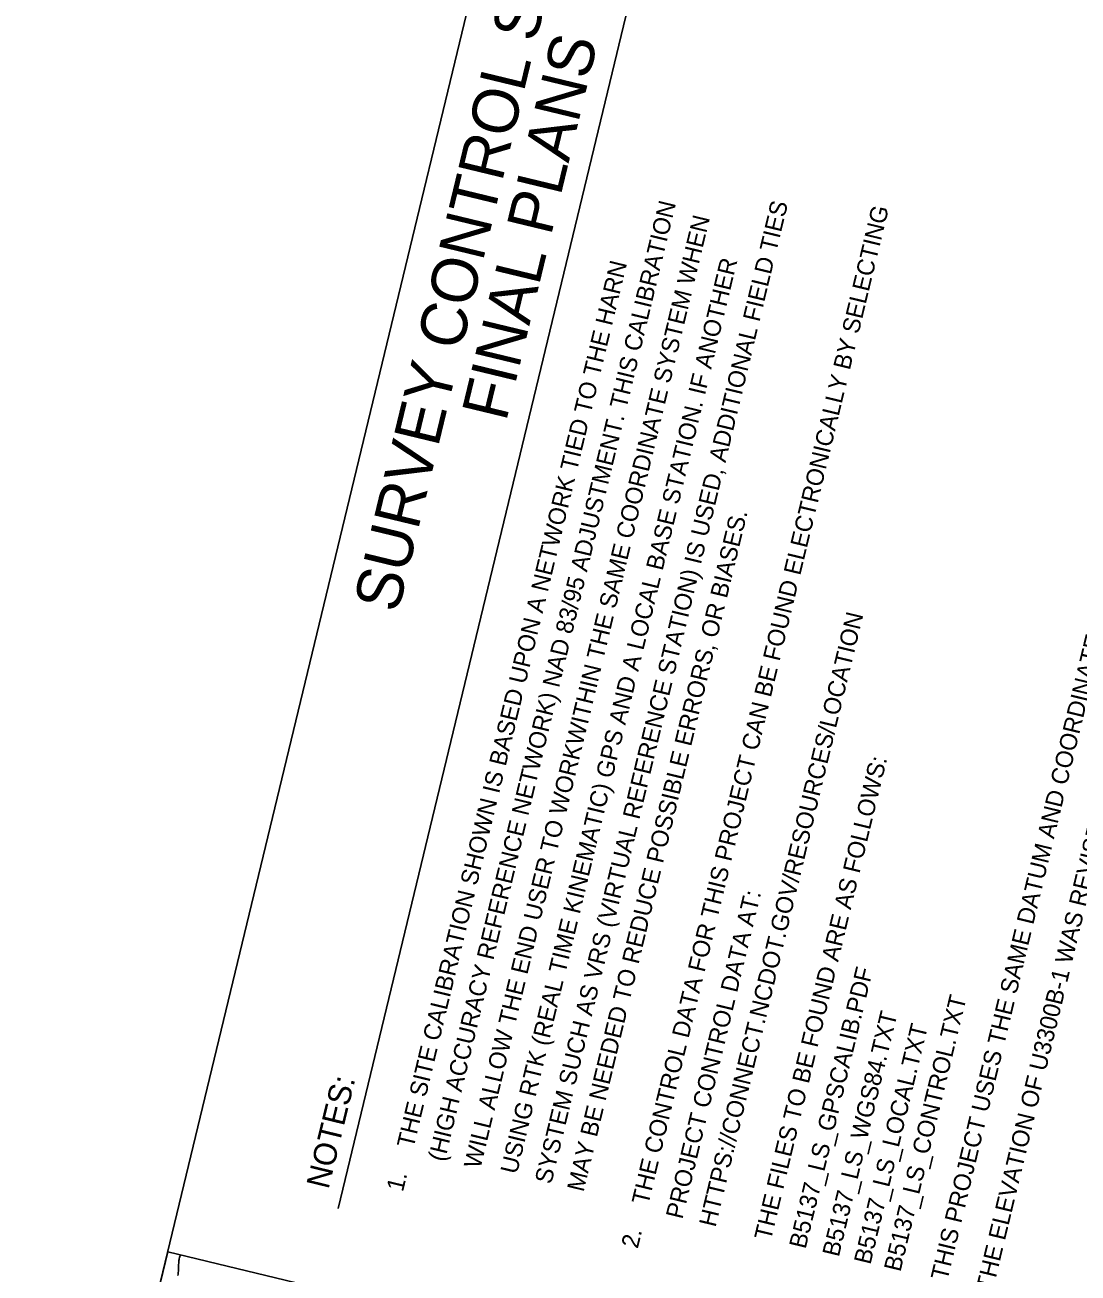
# Model space of a CAD drawing. Extents: x 1649669 to 1659218, y 588594 to 607900.
# Drawn here: x 1649669 to 1652859, y 599329 to 603109 of the extents above; entities that cross this region are included whole.
import ezdxf

# ---------------------------------------------------------------- set-up
doc = ezdxf.new("R2010")
doc.units = 0
for name, color, linetype in [('CTL Sheet Border CELL', 7, 'Continuous'), ('CTL Sheet Notes CELL', 7, 'Continuous'), ('Old_Level_29', 7, 'Continuous'), ('Old_Level_52', 7, 'Continuous')]:
    doc.layers.add(name, color=color, linetype=linetype)

msp = doc.modelspace()

# ---------------------------------------------------------------- linework, layer by layer
at = {"layer": 'CTL Sheet Border CELL'}
msp.add_lwpolyline([(1652117.6, 607744.3), (1649668.6, 597600.9), (1656768.8, 595886.6), (1659217.9, 606030)], close=True, dxfattribs=at)
at = {"layer": 'CTL Sheet Notes CELL'}
msp.add_line((1650617.4, 599524.6), (1652519.8, 607403.9), dxfattribs=at)
at = {"layer": 'Old_Level_29'}
for points in [[(1650137.2, 599375.6), (1650139.6, 599384.2)], [(1650132.1, 599321.7), (1650132.4, 599325.4), (1650133.4, 599339.7), (1650133.6, 599345.5), (1650134.1, 599353.1), (1650134.6, 599360.9), (1650134.9, 599364.5)], [(1650134.9, 599364.5), (1650135.2, 599366.5), (1650135.7, 599369.9), (1650136, 599371.6), (1650137.2, 599375.6)]]:
    msp.add_lwpolyline(points, dxfattribs=at)
at = {"layer": 'Old_Level_52'}
msp.add_lwpolyline([(1649668.6, 597600.9), (1650101.3, 599393.5), (1652635.5, 598781.6), (1652202.7, 596989.1)], close=True, dxfattribs=at)

# ---------------------------------------------------------------- texts
at = {"layer": 'CTL Sheet Border CELL'}
for s, p in [('SURVEY CONTROL SHEET', (1650798.4, 601324.6)), ('FINAL PLANS', (1651126.1, 601904.5))]:
    msp.add_text(s, height=139.13, rotation=76.4261, dxfattribs=at).set_placement(p)
at = {"layer": 'CTL Sheet Notes CELL'}
for s, height, rotation, p in [('(HIGH ACCURACY REFERENCE NETWORK) NAD 83/95 ADJUSTMENT. THIS CALIBRATION', 52.174, 76.4261, (1650940.1, 599663.7)), ('SYSTEM SUCH AS VRS (VIRTUAL REFERENCE STATION) IS USED, ADDITIONAL FIELD TIES', 52.174, 76.4261, (1651263.2, 599595.8)), ('2.    THE CONTROL DATA FOR THIS PROJECT CAN BE FOUND ELECTRONICALLY BY SELECTING', 52.174, 76.4261, (1651525.2, 599400.8)), ('WILL ALLOW THE END USER TO WORKWITHIN THE SAME COORDINATE SYSTEM WHEN', 52.174, 76.4261, (1651048.5, 599642.6)), ('3.    THIS PROJECT USES THE SAME DATUM AND COORDINATE SYSTEM AS TIP PROJECT U-3300B.', 52.174, 76.4261, (1652431.3, 599171.9)), ('1.    THE SITE CALIBRATION SHOWN IS BASED UPON A NETWORK TIED TO THE HARN', 52.174, 76.4261, (1650813.7, 599572.6)), ('USING RTK (REAL TIME KINEMATIC) GPS AND A LOCAL BASE STATION. IF ANOTHER', 52.174, 76.4261, (1651159, 599626.1)), ('4.    THE ELEVATION OF U3300B-1 WAS REVISED BASED ON LEVELS RUN FOR B-5137 PROJECT.', 52.174, 76.4261, (1652568.4, 599138.8)), ('MAY BE NEEDED TO REDUCE POSSIBLE ERRORS, OR BIASES.', 52.174, 76.4261, (1651360.9, 599572.3)), ('HTTPS://CONNECT.NCDOT.GOV/RESOURCES/LOCATION', 52.174, 76.4261, (1651760.8, 599465.6)), ('THE FILES TO BE FOUND ARE AS FOLLOWS:', 52.174, 76.4261, (1651928.4, 599425.1)), ('PROJECT CONTROL DATA AT:', 52.174, 76.4261, (1651660.3, 599489.8)), ('B5137_LS_GPSCALIB.PDF', 52.174, 76.4261, (1652033.7, 599399.7)), ('B5137_LS_CONTROL.TXT', 52.174, 76.4261, (1652321, 599330.3)), ('B5137_LS_WGS84.TXT', 52.174, 76.4261, (1652134.3, 599375.4)), ('B5137_LS_LOCAL.TXT', 52.174, 76.4261, (1652230.1, 599352.3)), ('NOTES:', 69.57, 76.3208, (1650588.1, 599580.4))]:
    msp.add_text(s, height=height, rotation=rotation, dxfattribs=at).set_placement(p)

doc.saveas('drawing.dxf')
